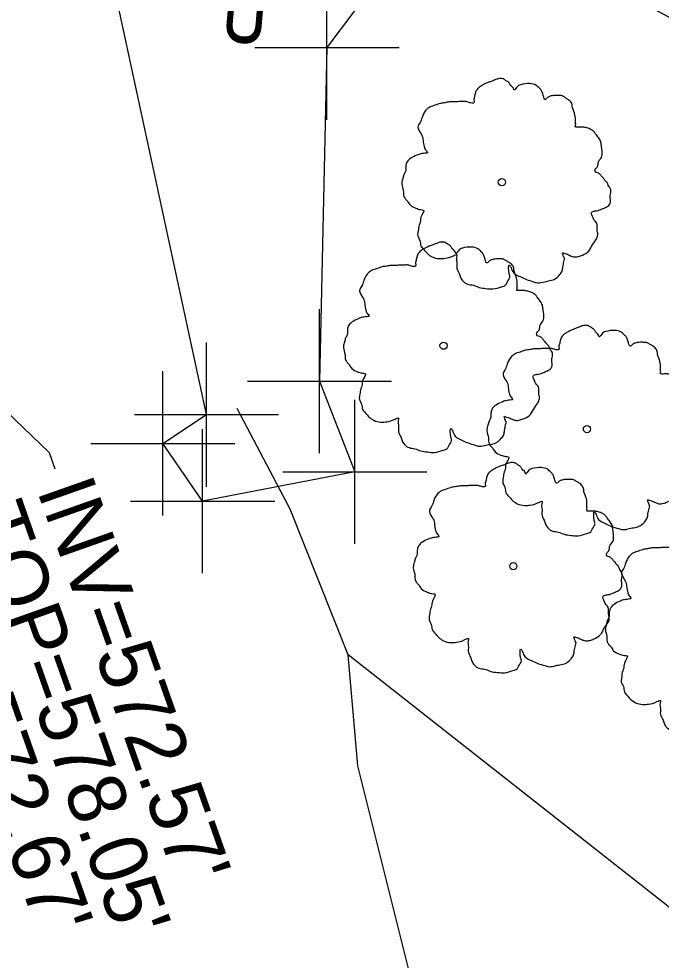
# Model space of a CAD drawing. Extents: x 2004847 to 2009016, y 1134161 to 1140101.
# Drawn here: x 2007601.4 to 2007646, y 1137837.3 to 1137902.6 of the extents above; entities that cross this region are included whole.
import ezdxf

# ---------------------------------------------------------------- set-up
doc = ezdxf.new("R2010")
doc.units = 0
for name, color, linetype in [('RD_EX_DR_Inlet_txCode', 7, 'Continuous'), ('RD_EX_DV_Prop_txCode', 7, 'Continuous'), ('RD_EX_H2O', 7, 'Continuous'), ('RD_EX_Misc', 7, 'Continuous'), ('RD_EX_VEG', 7, 'Continuous'), ('RD_Sketch3', 7, 'Continuous')]:
    doc.layers.add(name, color=color, linetype=linetype)

msp = doc.modelspace()

# ---------------------------------------------------------------- linework, layer by layer
at = {"layer": 'RD_EX_DR_Inlet_txCode'}
msp.add_lwpolyline([(2007572.498, 1137902.331), (2007603.497, 1137872.531), (2007603.895, 1137871.403)], dxfattribs=at)
at = {"layer": 'RD_EX_DV_Prop_txCode'}
for p, q in [((2007622.776, 1137895.63), (2007622.776, 1137905.63)), ((2007617.776, 1137900.63), (2007627.776, 1137900.63)), ((2007622.254, 1137872.485), (2007622.254, 1137882.485)), ((2007614.419, 1137870.162), (2007614.419, 1137880.162)), ((2007611.386, 1137868.169), (2007611.386, 1137878.169)), ((2007617.254, 1137877.485), (2007627.254, 1137877.485)), ((2007624.702, 1137866.19), (2007624.702, 1137876.19)), ((2007609.419, 1137875.162), (2007619.419, 1137875.162)), ((2007614.151, 1137864.159), (2007614.151, 1137874.159)), ((2007606.386, 1137873.169), (2007616.386, 1137873.169)), ((2007619.702, 1137871.19), (2007629.702, 1137871.19)), ((2007609.151, 1137869.159), (2007619.151, 1137869.159))]:
    msp.add_line(p, q, dxfattribs=at)
at = {"layer": 'RD_EX_H2O'}
for points in [[(2007661.393, 1137825.292), (2007646.407, 1137841.058), (2007624.242, 1137858.484), (2007620.215, 1137868.596), (2007616.545, 1137875.582)], [(2007631.362, 1137805.22), (2007630.861, 1137827.024), (2007624.915, 1137850.788), (2007624.242, 1137858.484)]]:
    msp.add_lwpolyline(points, dxfattribs=at)
at = {"layer": 'RD_EX_Misc'}
msp.add_lwpolyline([(2007614.151, 1137869.159), (2007611.386, 1137873.169), (2007614.419, 1137875.162), (2007606.944, 1137909.801), (2007609.9, 1137921.927), (2007617.543, 1137927.389), (2007622.84, 1137926.83), (2007626.274, 1137924.29), (2007656.867, 1137908.189), (2007662.538, 1137903.333), (2007668.453, 1137893.061), (2007664.156, 1137890.352), (2007656.754, 1137897.247), (2007636.864, 1137907.924), (2007628.602, 1137908.387), (2007622.776, 1137900.63), (2007622.254, 1137877.485), (2007624.702, 1137871.19), (2007614.151, 1137869.159)], dxfattribs=at)
at = {"layer": 'RD_EX_VEG'}
for centre, radius in [((2007634.907, 1137891.291), 0.25), ((2007634.894, 1137891.272), 0.0001), ((2007630.861, 1137879.947), 0.25), ((2007630.848, 1137879.928), 0.0001), ((2007640.807, 1137874.161), 0.25), ((2007640.794, 1137874.142), 0.0001), ((2007635.699, 1137864.65), 0.25), ((2007635.686, 1137864.631), 0.0001)]:
    msp.add_circle(centre, radius, dxfattribs=at)
for points in [[(2007635.039, 1137898.458), (2007634.739, 1137898.483), (2007634.414, 1137898.383), (2007634.164, 1137898.283), (2007633.939, 1137898.208), (2007633.715, 1137898.108), (2007633.415, 1137897.934), (2007633.19, 1137897.734), (2007633.065, 1137897.484), (2007633.015, 1137897.259), (2007632.965, 1137896.984), (2007632.965, 1137896.809), (2007632.84, 1137896.784), (2007632.69, 1137896.809), (2007632.44, 1137896.884), (2007632.19, 1137896.884), (2007631.94, 1137896.884), (2007631.59, 1137896.859), (2007631.241, 1137896.859), (2007630.966, 1137896.809), (2007630.641, 1137896.759), (2007630.266, 1137896.634), (2007629.916, 1137896.509), (2007629.616, 1137896.259), (2007629.366, 1137895.784), (2007629.241, 1137895.435), (2007629.092, 1137895.185), (2007629.241, 1137894.735), (2007629.416, 1137894.385), (2007629.441, 1137894.185), (2007629.516, 1137893.76), (2007629.616, 1137893.535), (2007629.741, 1137893.335), (2007629.666, 1137893.311), (2007629.291, 1137893.261), (2007628.992, 1137893.161), (2007628.567, 1137892.936), (2007628.342, 1137892.711), (2007628.242, 1137892.386), (2007628.217, 1137892.036), (2007628.117, 1137891.836), (2007628.042, 1137891.561), (2007628.017, 1137891.486), (2007627.967, 1137891.161), (2007628.067, 1137890.712), (2007628.092, 1137890.362), (2007628.217, 1137890.137), (2007628.367, 1137889.962), (2007628.542, 1137889.712), (2007628.942, 1137889.487), (2007629.266, 1137889.387), (2007629.466, 1137889.362), (2007629.291, 1137888.862), (2007629.241, 1137888.513), (2007629.117, 1137888.113), (2007629.117, 1137888.038), (2007629.067, 1137887.563), (2007629.216, 1137887.238), (2007629.291, 1137886.863), (2007629.466, 1137886.638), (2007629.741, 1137886.339), (2007630.066, 1137886.114), (2007630.566, 1137885.989), (2007630.966, 1137886.014), (2007631.541, 1137886.189), (2007631.79, 1137886.264), (2007631.765, 1137886.089), (2007631.79, 1137885.714), (2007631.79, 1137885.289), (2007631.94, 1137884.964), (2007632.04, 1137884.689), (2007632.19, 1137884.439), (2007632.515, 1137884.215), (2007632.915, 1137884.14), (2007633.34, 1137883.99), (2007633.79, 1137883.915), (2007634.289, 1137883.89), (2007634.889, 1137884.04), (2007635.164, 1137884.165), (2007635.264, 1137884.339), (2007635.464, 1137884.714), (2007635.414, 1137884.939), (2007635.439, 1137885.539), (2007635.539, 1137885.364), (2007635.714, 1137885.014), (2007636.213, 1137884.714), (2007636.613, 1137884.539), (2007637.088, 1137884.389), (2007637.388, 1137884.314), (2007637.863, 1137884.389), (2007638.238, 1137884.464), (2007638.612, 1137884.589), (2007638.912, 1137884.864), (2007639.087, 1137885.139), (2007639.137, 1137885.414), (2007639.212, 1137885.789), (2007639.262, 1137885.964)], [(2007639.262, 1137885.964), (2007639.187, 1137886.139), (2007639.137, 1137886.389), (2007639.212, 1137886.364), (2007639.387, 1137886.314), (2007639.662, 1137886.189), (2007639.887, 1137886.114), (2007640.212, 1137886.139), (2007640.487, 1137886.239), (2007640.936, 1137886.514), (2007641.211, 1137886.988), (2007641.486, 1137887.388), (2007641.561, 1137887.713), (2007641.511, 1137887.938), (2007641.486, 1137888.438), (2007641.286, 1137888.688), (2007641.236, 1137888.812), (2007641.136, 1137889.212), (2007641.211, 1137889.262), (2007641.486, 1137889.312), (2007641.861, 1137889.437), (2007642.136, 1137889.562), (2007642.361, 1137889.737), (2007642.436, 1137889.962), (2007642.411, 1137890.362), (2007642.461, 1137890.762), (2007642.386, 1137890.912), (2007642.286, 1137891.061), (2007642.211, 1137891.261), (2007642.061, 1137891.411), (2007641.961, 1137891.561), (2007641.861, 1137891.661), (2007641.736, 1137891.811), (2007641.561, 1137891.936), (2007641.411, 1137891.986), (2007641.361, 1137892.136), (2007641.511, 1137892.336), (2007641.561, 1137892.436), (2007641.586, 1137892.661), (2007641.811, 1137893.011), (2007641.861, 1137893.41), (2007641.811, 1137893.835), (2007641.761, 1137894.11), (2007641.611, 1137894.385), (2007641.411, 1137894.635), (2007641.286, 1137894.81), (2007641.111, 1137894.935), (2007640.786, 1137895.06), (2007640.537, 1137895.11), (2007640.187, 1137895.11), (2007639.987, 1137895.16), (2007640.012, 1137895.21), (2007640.012, 1137895.36), (2007640.012, 1137895.635), (2007639.937, 1137896.084), (2007639.787, 1137896.584), (2007639.787, 1137896.609), (2007639.687, 1137896.859), (2007639.462, 1137897.059), (2007639.287, 1137897.159), (2007639.087, 1137897.284), (2007638.837, 1137897.309), (2007638.537, 1137897.309), (2007638.263, 1137897.259), (2007638.063, 1137897.159), (2007637.888, 1137897.034), (2007637.813, 1137897.184), (2007637.713, 1137897.484), (2007637.663, 1137897.634), (2007637.513, 1137897.809), (2007637.288, 1137898.008), (2007636.838, 1137898.133), (2007636.213, 1137898.058), (2007635.914, 1137897.859), (2007635.764, 1137897.684), (2007635.714, 1137897.809), (2007635.514, 1137898.008), (2007635.414, 1137898.183), (2007635.239, 1137898.308), (2007635.089, 1137898.408), (2007634.989, 1137898.458)], [(2007630.993, 1137887.114), (2007630.693, 1137887.139), (2007630.368, 1137887.039), (2007630.118, 1137886.939), (2007629.893, 1137886.864), (2007629.669, 1137886.764), (2007629.369, 1137886.59), (2007629.144, 1137886.39), (2007629.019, 1137886.14), (2007628.969, 1137885.915), (2007628.919, 1137885.64), (2007628.919, 1137885.465), (2007628.794, 1137885.44), (2007628.644, 1137885.465), (2007628.394, 1137885.54), (2007628.144, 1137885.54), (2007627.894, 1137885.54), (2007627.544, 1137885.515), (2007627.195, 1137885.515), (2007626.92, 1137885.465), (2007626.595, 1137885.415), (2007626.22, 1137885.29), (2007625.87, 1137885.165), (2007625.57, 1137884.915), (2007625.32, 1137884.44), (2007625.195, 1137884.091), (2007625.046, 1137883.841), (2007625.195, 1137883.391), (2007625.37, 1137883.041), (2007625.395, 1137882.841), (2007625.47, 1137882.416), (2007625.57, 1137882.191), (2007625.695, 1137881.991), (2007625.62, 1137881.967), (2007625.245, 1137881.917), (2007624.946, 1137881.817), (2007624.521, 1137881.592), (2007624.296, 1137881.367), (2007624.196, 1137881.042), (2007624.171, 1137880.692), (2007624.071, 1137880.492), (2007623.996, 1137880.217), (2007623.971, 1137880.142), (2007623.921, 1137879.817), (2007624.021, 1137879.368), (2007624.046, 1137879.018), (2007624.171, 1137878.793), (2007624.321, 1137878.618), (2007624.496, 1137878.368), (2007624.896, 1137878.143), (2007625.22, 1137878.043), (2007625.42, 1137878.018), (2007625.245, 1137877.518), (2007625.195, 1137877.169), (2007625.071, 1137876.769), (2007625.071, 1137876.694), (2007625.021, 1137876.219), (2007625.17, 1137875.894), (2007625.245, 1137875.519), (2007625.42, 1137875.294), (2007625.695, 1137874.995), (2007626.02, 1137874.77), (2007626.52, 1137874.645), (2007626.92, 1137874.67), (2007627.495, 1137874.845), (2007627.744, 1137874.92), (2007627.719, 1137874.745), (2007627.744, 1137874.37), (2007627.744, 1137873.945), (2007627.894, 1137873.62), (2007627.994, 1137873.345), (2007628.144, 1137873.095), (2007628.469, 1137872.871), (2007628.869, 1137872.796), (2007629.294, 1137872.646), (2007629.744, 1137872.571), (2007630.243, 1137872.546), (2007630.843, 1137872.696), (2007631.118, 1137872.821), (2007631.218, 1137872.995), (2007631.418, 1137873.37), (2007631.368, 1137873.595), (2007631.393, 1137874.195), (2007631.493, 1137874.02), (2007631.668, 1137873.67), (2007632.167, 1137873.37), (2007632.567, 1137873.195), (2007633.042, 1137873.045), (2007633.342, 1137872.97), (2007633.817, 1137873.045), (2007634.192, 1137873.12), (2007634.566, 1137873.245), (2007634.866, 1137873.52), (2007635.041, 1137873.795), (2007635.091, 1137874.07), (2007635.166, 1137874.445), (2007635.216, 1137874.62)], [(2007635.216, 1137874.62), (2007635.141, 1137874.795), (2007635.091, 1137875.045), (2007635.166, 1137875.02), (2007635.341, 1137874.97), (2007635.616, 1137874.845), (2007635.841, 1137874.77), (2007636.166, 1137874.795), (2007636.441, 1137874.895), (2007636.89, 1137875.17), (2007637.165, 1137875.644), (2007637.44, 1137876.044), (2007637.515, 1137876.369), (2007637.465, 1137876.594), (2007637.44, 1137877.094), (2007637.24, 1137877.344), (2007637.19, 1137877.468), (2007637.09, 1137877.868), (2007637.165, 1137877.918), (2007637.44, 1137877.968), (2007637.815, 1137878.093), (2007638.09, 1137878.218), (2007638.315, 1137878.393), (2007638.39, 1137878.618), (2007638.365, 1137879.018), (2007638.415, 1137879.418), (2007638.34, 1137879.568), (2007638.24, 1137879.717), (2007638.165, 1137879.917), (2007638.015, 1137880.067), (2007637.915, 1137880.217), (2007637.815, 1137880.317), (2007637.69, 1137880.467), (2007637.515, 1137880.592), (2007637.365, 1137880.642), (2007637.315, 1137880.792), (2007637.465, 1137880.992), (2007637.515, 1137881.092), (2007637.54, 1137881.317), (2007637.765, 1137881.667), (2007637.815, 1137882.066), (2007637.765, 1137882.491), (2007637.715, 1137882.766), (2007637.565, 1137883.041), (2007637.365, 1137883.291), (2007637.24, 1137883.466), (2007637.065, 1137883.591), (2007636.74, 1137883.716), (2007636.491, 1137883.766), (2007636.141, 1137883.766), (2007635.941, 1137883.816), (2007635.966, 1137883.866), (2007635.966, 1137884.016), (2007635.966, 1137884.291), (2007635.891, 1137884.74), (2007635.741, 1137885.24), (2007635.741, 1137885.265), (2007635.641, 1137885.515), (2007635.416, 1137885.715), (2007635.241, 1137885.815), (2007635.041, 1137885.94), (2007634.791, 1137885.965), (2007634.491, 1137885.965), (2007634.217, 1137885.915), (2007634.017, 1137885.815), (2007633.842, 1137885.69), (2007633.767, 1137885.84), (2007633.667, 1137886.14), (2007633.617, 1137886.29), (2007633.467, 1137886.465), (2007633.242, 1137886.664), (2007632.792, 1137886.789), (2007632.167, 1137886.714), (2007631.868, 1137886.515), (2007631.718, 1137886.34), (2007631.668, 1137886.465), (2007631.468, 1137886.664), (2007631.368, 1137886.839), (2007631.193, 1137886.964), (2007631.043, 1137887.064), (2007630.943, 1137887.114)], [(2007640.939, 1137881.328), (2007640.639, 1137881.353), (2007640.314, 1137881.253), (2007640.064, 1137881.153), (2007639.839, 1137881.078), (2007639.615, 1137880.978), (2007639.315, 1137880.804), (2007639.09, 1137880.604), (2007638.965, 1137880.354), (2007638.915, 1137880.129), (2007638.865, 1137879.854), (2007638.865, 1137879.679), (2007638.74, 1137879.654), (2007638.59, 1137879.679), (2007638.34, 1137879.754), (2007638.09, 1137879.754), (2007637.84, 1137879.754), (2007637.49, 1137879.729), (2007637.141, 1137879.729), (2007636.866, 1137879.679), (2007636.541, 1137879.629), (2007636.166, 1137879.504), (2007635.816, 1137879.379), (2007635.516, 1137879.129), (2007635.266, 1137878.654), (2007635.141, 1137878.305), (2007634.992, 1137878.055), (2007635.141, 1137877.605), (2007635.316, 1137877.255), (2007635.341, 1137877.055), (2007635.416, 1137876.63), (2007635.516, 1137876.405), (2007635.641, 1137876.205), (2007635.566, 1137876.181), (2007635.191, 1137876.131), (2007634.892, 1137876.031), (2007634.467, 1137875.806), (2007634.242, 1137875.581), (2007634.142, 1137875.256), (2007634.117, 1137874.906), (2007634.017, 1137874.706), (2007633.942, 1137874.431), (2007633.917, 1137874.356), (2007633.867, 1137874.031), (2007633.967, 1137873.582), (2007633.992, 1137873.232), (2007634.117, 1137873.007), (2007634.267, 1137872.832), (2007634.442, 1137872.582), (2007634.842, 1137872.357), (2007635.166, 1137872.257), (2007635.366, 1137872.232), (2007635.191, 1137871.732), (2007635.141, 1137871.383), (2007635.017, 1137870.983), (2007635.017, 1137870.908), (2007634.967, 1137870.433), (2007635.116, 1137870.108), (2007635.191, 1137869.733), (2007635.366, 1137869.508), (2007635.641, 1137869.209), (2007635.966, 1137868.984), (2007636.466, 1137868.859), (2007636.866, 1137868.884), (2007637.441, 1137869.059), (2007637.69, 1137869.134), (2007637.665, 1137868.959), (2007637.69, 1137868.584), (2007637.69, 1137868.159), (2007637.84, 1137867.834), (2007637.94, 1137867.559), (2007638.09, 1137867.309), (2007638.415, 1137867.085), (2007638.815, 1137867.01), (2007639.24, 1137866.86), (2007639.69, 1137866.785), (2007640.189, 1137866.76), (2007640.789, 1137866.91), (2007641.064, 1137867.035), (2007641.164, 1137867.209), (2007641.364, 1137867.584), (2007641.314, 1137867.809), (2007641.339, 1137868.409), (2007641.439, 1137868.234), (2007641.614, 1137867.884), (2007642.113, 1137867.584), (2007642.513, 1137867.409), (2007642.988, 1137867.259), (2007643.288, 1137867.184), (2007643.763, 1137867.259), (2007644.138, 1137867.334), (2007644.512, 1137867.459), (2007644.812, 1137867.734), (2007644.987, 1137868.009), (2007645.037, 1137868.284), (2007645.112, 1137868.659), (2007645.162, 1137868.834)], [(2007645.162, 1137868.834), (2007645.087, 1137869.009), (2007645.037, 1137869.259), (2007645.112, 1137869.234), (2007645.287, 1137869.184), (2007645.562, 1137869.059), (2007645.787, 1137868.984), (2007646.112, 1137869.009), (2007646.387, 1137869.109), (2007646.836, 1137869.384), (2007647.111, 1137869.858), (2007647.386, 1137870.258), (2007647.461, 1137870.583), (2007647.411, 1137870.808), (2007647.386, 1137871.308), (2007647.186, 1137871.558), (2007647.136, 1137871.682), (2007647.036, 1137872.082), (2007647.111, 1137872.132), (2007647.386, 1137872.182), (2007647.761, 1137872.307), (2007648.036, 1137872.432), (2007648.261, 1137872.607), (2007648.336, 1137872.832), (2007648.311, 1137873.232), (2007648.361, 1137873.632), (2007648.286, 1137873.782), (2007648.186, 1137873.931), (2007648.111, 1137874.131), (2007647.961, 1137874.281), (2007647.861, 1137874.431), (2007647.761, 1137874.531), (2007647.636, 1137874.681), (2007647.461, 1137874.806), (2007647.311, 1137874.856), (2007647.261, 1137875.006), (2007647.411, 1137875.206), (2007647.461, 1137875.306), (2007647.486, 1137875.531), (2007647.711, 1137875.881), (2007647.761, 1137876.28), (2007647.711, 1137876.705), (2007647.661, 1137876.98), (2007647.511, 1137877.255), (2007647.311, 1137877.505), (2007647.186, 1137877.68), (2007647.011, 1137877.805), (2007646.686, 1137877.93), (2007646.437, 1137877.98), (2007646.087, 1137877.98), (2007645.887, 1137878.03), (2007645.912, 1137878.08), (2007645.912, 1137878.23), (2007645.912, 1137878.505), (2007645.837, 1137878.954), (2007645.687, 1137879.454), (2007645.687, 1137879.479), (2007645.587, 1137879.729), (2007645.362, 1137879.929), (2007645.187, 1137880.029), (2007644.987, 1137880.154), (2007644.737, 1137880.179), (2007644.437, 1137880.179), (2007644.163, 1137880.129), (2007643.963, 1137880.029), (2007643.788, 1137879.904), (2007643.713, 1137880.054), (2007643.613, 1137880.354), (2007643.563, 1137880.504), (2007643.413, 1137880.679), (2007643.188, 1137880.878), (2007642.738, 1137881.003), (2007642.113, 1137880.928), (2007641.814, 1137880.729), (2007641.664, 1137880.554), (2007641.614, 1137880.679), (2007641.414, 1137880.878), (2007641.314, 1137881.053), (2007641.139, 1137881.178), (2007640.989, 1137881.278), (2007640.889, 1137881.328)], [(2007635.831, 1137871.817), (2007635.531, 1137871.842), (2007635.206, 1137871.742), (2007634.956, 1137871.642), (2007634.731, 1137871.567), (2007634.507, 1137871.467), (2007634.207, 1137871.292), (2007633.982, 1137871.093), (2007633.857, 1137870.843), (2007633.807, 1137870.618), (2007633.757, 1137870.343), (2007633.757, 1137870.168), (2007633.632, 1137870.143), (2007633.482, 1137870.168), (2007633.232, 1137870.243), (2007632.982, 1137870.243), (2007632.732, 1137870.243), (2007632.382, 1137870.218), (2007632.033, 1137870.218), (2007631.758, 1137870.168), (2007631.433, 1137870.118), (2007631.058, 1137869.993), (2007630.708, 1137869.868), (2007630.408, 1137869.618), (2007630.158, 1137869.143), (2007630.033, 1137868.794), (2007629.884, 1137868.544), (2007630.033, 1137868.094), (2007630.208, 1137867.744), (2007630.233, 1137867.544), (2007630.308, 1137867.119), (2007630.408, 1137866.894), (2007630.533, 1137866.694), (2007630.458, 1137866.67), (2007630.083, 1137866.62), (2007629.784, 1137866.52), (2007629.359, 1137866.295), (2007629.134, 1137866.07), (2007629.034, 1137865.745), (2007629.009, 1137865.395), (2007628.909, 1137865.195), (2007628.834, 1137864.92), (2007628.809, 1137864.845), (2007628.759, 1137864.52), (2007628.859, 1137864.071), (2007628.884, 1137863.721), (2007629.009, 1137863.496), (2007629.159, 1137863.321), (2007629.334, 1137863.071), (2007629.734, 1137862.846), (2007630.058, 1137862.746), (2007630.258, 1137862.721), (2007630.083, 1137862.221), (2007630.033, 1137861.872), (2007629.909, 1137861.472), (2007629.909, 1137861.397), (2007629.859, 1137860.922), (2007630.008, 1137860.597), (2007630.083, 1137860.222), (2007630.258, 1137859.997), (2007630.533, 1137859.698), (2007630.858, 1137859.473), (2007631.358, 1137859.348), (2007631.758, 1137859.373), (2007632.333, 1137859.548), (2007632.582, 1137859.623), (2007632.557, 1137859.448), (2007632.582, 1137859.073), (2007632.582, 1137858.648), (2007632.732, 1137858.323), (2007632.832, 1137858.048), (2007632.982, 1137857.798), (2007633.307, 1137857.573), (2007633.707, 1137857.498), (2007634.132, 1137857.349), (2007634.582, 1137857.274), (2007635.081, 1137857.249), (2007635.681, 1137857.398), (2007635.956, 1137857.523), (2007636.056, 1137857.698), (2007636.256, 1137858.073), (2007636.206, 1137858.298), (2007636.231, 1137858.898), (2007636.331, 1137858.723), (2007636.506, 1137858.373), (2007637.005, 1137858.073), (2007637.405, 1137857.898), (2007637.88, 1137857.748), (2007638.18, 1137857.673), (2007638.655, 1137857.748), (2007639.03, 1137857.823), (2007639.404, 1137857.948), (2007639.704, 1137858.223), (2007639.879, 1137858.498), (2007639.929, 1137858.773), (2007640.004, 1137859.148), (2007640.054, 1137859.323)], [(2007640.054, 1137859.323), (2007639.979, 1137859.498), (2007639.929, 1137859.748), (2007640.004, 1137859.722), (2007640.179, 1137859.673), (2007640.454, 1137859.548), (2007640.679, 1137859.473), (2007641.004, 1137859.498), (2007641.279, 1137859.598), (2007641.728, 1137859.873), (2007642.003, 1137860.347), (2007642.278, 1137860.747), (2007642.353, 1137861.072), (2007642.303, 1137861.297), (2007642.278, 1137861.797), (2007642.078, 1137862.046), (2007642.028, 1137862.171), (2007641.928, 1137862.571), (2007642.003, 1137862.621), (2007642.278, 1137862.671), (2007642.653, 1137862.796), (2007642.928, 1137862.921), (2007643.153, 1137863.096), (2007643.228, 1137863.321), (2007643.203, 1137863.721), (2007643.253, 1137864.121), (2007643.178, 1137864.271), (2007643.078, 1137864.42), (2007643.003, 1137864.62), (2007642.853, 1137864.77), (2007642.753, 1137864.92), (2007642.653, 1137865.02), (2007642.528, 1137865.17), (2007642.353, 1137865.295), (2007642.203, 1137865.345), (2007642.153, 1137865.495), (2007642.303, 1137865.695), (2007642.353, 1137865.795), (2007642.378, 1137866.02), (2007642.603, 1137866.37), (2007642.653, 1137866.769), (2007642.603, 1137867.194), (2007642.553, 1137867.469), (2007642.403, 1137867.744), (2007642.203, 1137867.994), (2007642.078, 1137868.169), (2007641.903, 1137868.294), (2007641.578, 1137868.419), (2007641.329, 1137868.469), (2007640.979, 1137868.469), (2007640.779, 1137868.519), (2007640.804, 1137868.569), (2007640.804, 1137868.719), (2007640.804, 1137868.994), (2007640.729, 1137869.443), (2007640.579, 1137869.943), (2007640.579, 1137869.968), (2007640.479, 1137870.218), (2007640.254, 1137870.418), (2007640.079, 1137870.518), (2007639.879, 1137870.643), (2007639.629, 1137870.668), (2007639.329, 1137870.668), (2007639.055, 1137870.618), (2007638.855, 1137870.518), (2007638.68, 1137870.393), (2007638.605, 1137870.543), (2007638.505, 1137870.843), (2007638.455, 1137870.993), (2007638.305, 1137871.167), (2007638.08, 1137871.367), (2007637.63, 1137871.492), (2007637.005, 1137871.417), (2007636.706, 1137871.218), (2007636.556, 1137871.043), (2007636.506, 1137871.167), (2007636.306, 1137871.367), (2007636.206, 1137871.542), (2007636.031, 1137871.667), (2007635.881, 1137871.767), (2007635.781, 1137871.817)], [(2007649.154, 1137867.517), (2007648.854, 1137867.542), (2007648.529, 1137867.442), (2007648.279, 1137867.342), (2007648.054, 1137867.267), (2007647.83, 1137867.167), (2007647.53, 1137866.993), (2007647.305, 1137866.793), (2007647.18, 1137866.543), (2007647.13, 1137866.318), (2007647.08, 1137866.043), (2007647.08, 1137865.868), (2007646.955, 1137865.843), (2007646.805, 1137865.868), (2007646.555, 1137865.943), (2007646.305, 1137865.943), (2007646.055, 1137865.943), (2007645.705, 1137865.918), (2007645.356, 1137865.918), (2007645.081, 1137865.868), (2007644.756, 1137865.818), (2007644.381, 1137865.693), (2007644.031, 1137865.568), (2007643.731, 1137865.318), (2007643.481, 1137864.843), (2007643.356, 1137864.494), (2007643.207, 1137864.244), (2007643.356, 1137863.794), (2007643.531, 1137863.444), (2007643.556, 1137863.244), (2007643.631, 1137862.819), (2007643.731, 1137862.594), (2007643.856, 1137862.394), (2007643.781, 1137862.37), (2007643.406, 1137862.32), (2007643.107, 1137862.22), (2007642.682, 1137861.995), (2007642.457, 1137861.77), (2007642.357, 1137861.445), (2007642.332, 1137861.095), (2007642.232, 1137860.895), (2007642.157, 1137860.62), (2007642.132, 1137860.545), (2007642.082, 1137860.22), (2007642.182, 1137859.771), (2007642.207, 1137859.421), (2007642.332, 1137859.196), (2007642.482, 1137859.021), (2007642.657, 1137858.771), (2007643.057, 1137858.546), (2007643.381, 1137858.446), (2007643.581, 1137858.421), (2007643.406, 1137857.921), (2007643.356, 1137857.572), (2007643.232, 1137857.172), (2007643.232, 1137857.097), (2007643.182, 1137856.622), (2007643.331, 1137856.297), (2007643.406, 1137855.922), (2007643.581, 1137855.697), (2007643.856, 1137855.398), (2007644.181, 1137855.173), (2007644.681, 1137855.048), (2007645.081, 1137855.073), (2007645.656, 1137855.248), (2007645.905, 1137855.323), (2007645.88, 1137855.148), (2007645.905, 1137854.773), (2007645.905, 1137854.348), (2007646.055, 1137854.023), (2007646.155, 1137853.748), (2007646.305, 1137853.498), (2007646.63, 1137853.274), (2007647.03, 1137853.199), (2007647.455, 1137853.049), (2007647.905, 1137852.974), (2007648.404, 1137852.949), (2007649.004, 1137853.099), (2007649.279, 1137853.224), (2007649.379, 1137853.398), (2007649.579, 1137853.773), (2007649.529, 1137853.998), (2007649.554, 1137854.598), (2007649.654, 1137854.423), (2007649.829, 1137854.073), (2007650.328, 1137853.773), (2007650.728, 1137853.598), (2007651.203, 1137853.448), (2007651.503, 1137853.373), (2007651.978, 1137853.448), (2007652.353, 1137853.523), (2007652.727, 1137853.648), (2007653.027, 1137853.923), (2007653.202, 1137854.198), (2007653.252, 1137854.473), (2007653.327, 1137854.848), (2007653.377, 1137855.023)]]:
    msp.add_spline(points, degree=3, dxfattribs=at)

# ---------------------------------------------------------------- texts
at = {"layer": 'RD_EX_DR_Inlet_txCode'}
for s, p in [("INV=572.57'", (2007602.638, 1137869.925)), ("TOP=578.05'", (2007597.779, 1137868.201)), ("INV=572.67'", (2007593.072, 1137866.405))]:
    msp.add_text(s, height=4.00001, rotation=289.44941, dxfattribs=at).set_placement(p)
at = {"layer": 'RD_Sketch3'}
msp.add_text('RIP RAP', height=4, rotation=265.01392, dxfattribs=at).set_placement((2007615.981, 1137922.187))

doc.saveas('drawing.dxf')
